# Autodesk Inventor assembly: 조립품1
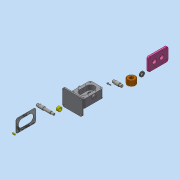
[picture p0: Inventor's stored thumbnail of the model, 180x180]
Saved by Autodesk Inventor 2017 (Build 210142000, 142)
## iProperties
Part Number: 조립품1
Material: 일반
Document SubType Name: Assembly
Designer: MRC
Author: MRC
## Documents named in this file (11)
- C:\Users\MRC\Desktop\700407V1045\조립품1.iam
- C:\Users\MRC\Desktop\700407V1045\Ű 6 x 6 x 18.ipt
- C:\Users\MRC\Desktop\700407V1045\개스킷.ipt
- C:\Users\MRC\Desktop\700407V1045\메인축.ipt
- C:\Users\MRC\Desktop\700407V1045\베어링부시.ipt
- C:\Users\MRC\Desktop\700407V1045\본체.ipt
- C:\Users\MRC\Desktop\700407V1045\볼트 M5.ipt
- C:\Users\MRC\Desktop\700407V1045\서브축.ipt
- C:\Users\MRC\Desktop\700407V1045\스퍼기어.ipt
- C:\Users\MRC\Desktop\700407V1045\오일 실 16 28 7.ipt
- C:\Users\MRC\Desktop\700407V1045\커버.ipt
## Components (2 placed, 2 different names)
1. Ű 6 x 6 x 18:1
2. 개스킷:1
